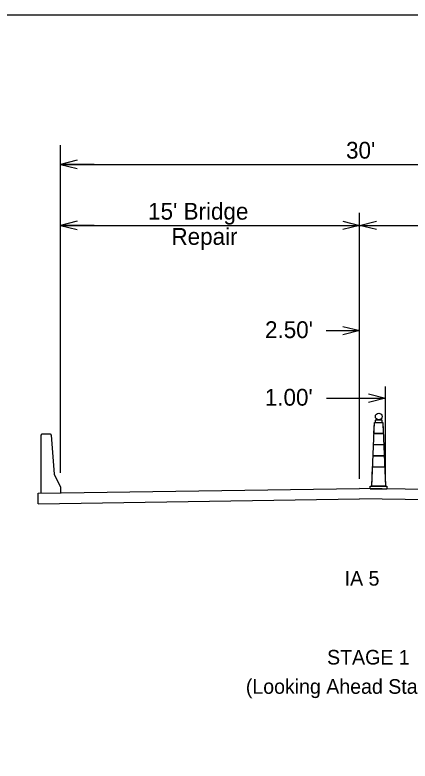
# Model space of a CAD drawing. Extents: x 10133 to 81668, y 4692 to 11018.
# Drawn here: x 11233 to 11768, y 8934 to 9944 of the extents above; entities that cross this region are included whole.
import ezdxf

# ---------------------------------------------------------------- set-up
doc = ezdxf.new("R2010")
doc.units = 0
for name, color, linetype in [('Level 7', 7, 'Continuous'), ('SheetBorder', 7, 'Continuous'), ('Stage_Construction Traffic Control', 7, 'Continuous')]:
    doc.layers.add(name, color=color, linetype=linetype)

msp = doc.modelspace()

# ---------------------------------------------------------------- linework, layer by layer
at = {"layer": 'Level 7'}
for p, q in [((11295, 9324.2), (11295, 9767.9)), ((11295, 9741.7), (12105, 9741.7)), ((11340.4, 9741.7), (11295, 9741.7)), ((11700, 9316.2), (11700, 9676.2)), ((11295, 9659), (11700, 9659)), ((11340.4, 9659), (11295, 9659)), ((11677.3, 9664.7), (11700, 9659)), ((11700, 9659), (11677.3, 9653.4)), ((11700, 9659), (11722.7, 9664.7)), ((11700, 9659), (12105, 9659)), ((11722.7, 9653.4), (11700, 9659)), ((11654.7, 9516.8), (11700.1, 9516.8)), ((11735.1, 9311.6), (11735.1, 9441)), ((11655.1, 9425.3), (11735, 9425.3)), ((11268.8, 9375), (11270.1, 9376.9)), ((11268.8, 9296.6), (11268.8, 9375)), ((11270.1, 9376.9), (11281, 9377.1)), ((11281, 9377.1), (11282.3, 9375.3)), ((11282.3, 9375.3), (11286.5, 9322.2)), ((11286.5, 9322.2), (11295, 9304.9)), ((11264.6, 9296.5), (11700, 9303.1)), ((11295, 9304.9), (11295.1, 9297)), ((12135.4, 9296.5), (11700, 9303.1)), ((11264.6, 9282.3), (11264.6, 9296.5)), ((11264.6, 9282.3), (11700, 9288.8)), ((12135.4, 9282.3), (11700, 9288.8))]:
    msp.add_line(p, q, dxfattribs=at)
for points in [[(11317.7, 9747.4), (11295, 9741.7), (11317.7, 9736.1)], [(11317.7, 9664.7), (11295, 9659), (11317.7, 9653.4)], [(11677.4, 9522.4), (11700.1, 9516.8), (11677.4, 9511.1)], [(11712.2, 9431), (11735, 9425.3), (11712.2, 9419.6)]]:
    msp.add_lwpolyline(points, dxfattribs=at)
at = {"layer": 'SheetBorder'}
msp.add_lwpolyline([(10132.5, 9944), (13267.5, 9944), (13267.5, 7924), (10132.5, 7924)], close=True, dxfattribs=at)
at = {"layer": 'Stage_Construction Traffic Control'}
for p, q in [((11716.3, 9306.2), (11720.1, 9392.4)), ((11719.4, 9377.4), (11720.1, 9392.4)), ((11720.1, 9392.4), (11731.3, 9392.4)), ((11720.1, 9392.4), (11731.3, 9392.4)), ((11731.3, 9392.4), (11735.1, 9306.2)), ((11731.3, 9392.4), (11732, 9377.4)), ((11719.4, 9377.4), (11732, 9377.4)), ((11732, 9377.4), (11719.4, 9377.4)), ((11718.1, 9347.4), (11718.8, 9362.4)), ((11718.8, 9362.4), (11732.6, 9362.4)), ((11718.8, 9362.4), (11732.6, 9362.4)), ((11732.6, 9362.4), (11733.3, 9347.4)), ((11718.1, 9347.4), (11733.3, 9347.4)), ((11733.3, 9347.4), (11718.1, 9347.4)), ((11716.3, 9306.2), (11717.5, 9332.4)), ((11717.5, 9332.4), (11733.9, 9332.4)), ((11717.5, 9332.4), (11733.9, 9332.4)), ((11733.9, 9332.4), (11735.1, 9306.2)), ((11714.4, 9306.2), (11736.9, 9306.2)), ((11714.4, 9302.4), (11714.4, 9306.2)), ((11714.4, 9302.4), (11736.9, 9302.4)), ((11735.1, 9306.2), (11716.3, 9306.2)), ((11736.9, 9306.2), (11736.9, 9302.4))]:
    msp.add_line(p, q, dxfattribs=at)
msp.add_lwpolyline([(11730.6, 9395.4), (11721, 9395.4), (11721, 9392.4), (11730.6, 9392.4)], close=True, dxfattribs=at)
msp.add_circle((11725.8, 9400.5), 4.5, dxfattribs=at)

# ---------------------------------------------------------------- texts
at = {"layer": 'Level 7'}
for s, height, p in [("30'", 22.71, (11681.6, 9749.5)), ("15' Bridge", 22.71, (11413.6, 9666.9)), ('Repair', 22.71, (11445.2, 9632.8)), ("2.50'", 22.71, (11571.9, 9506.6)), ("1.00'", 22.71, (11571.6, 9415.1)), ('IA 5', 19.8, (11679.7, 9171.5)), ('STAGE 1', 19.8, (11655.9, 9064.7)), ('(Looking Ahead Station)', 19.8, (11545.9, 9025.1))]:
    msp.add_text(s, height=height, dxfattribs=at).set_placement(p)

doc.saveas('drawing.dxf')
